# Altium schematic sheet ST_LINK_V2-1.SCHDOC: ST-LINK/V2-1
size A4; DocumentNumber: MB1263; Revision: C-04; SheetNumber: 10; SheetTotal: 11; Project: STM32MP157-EVAL
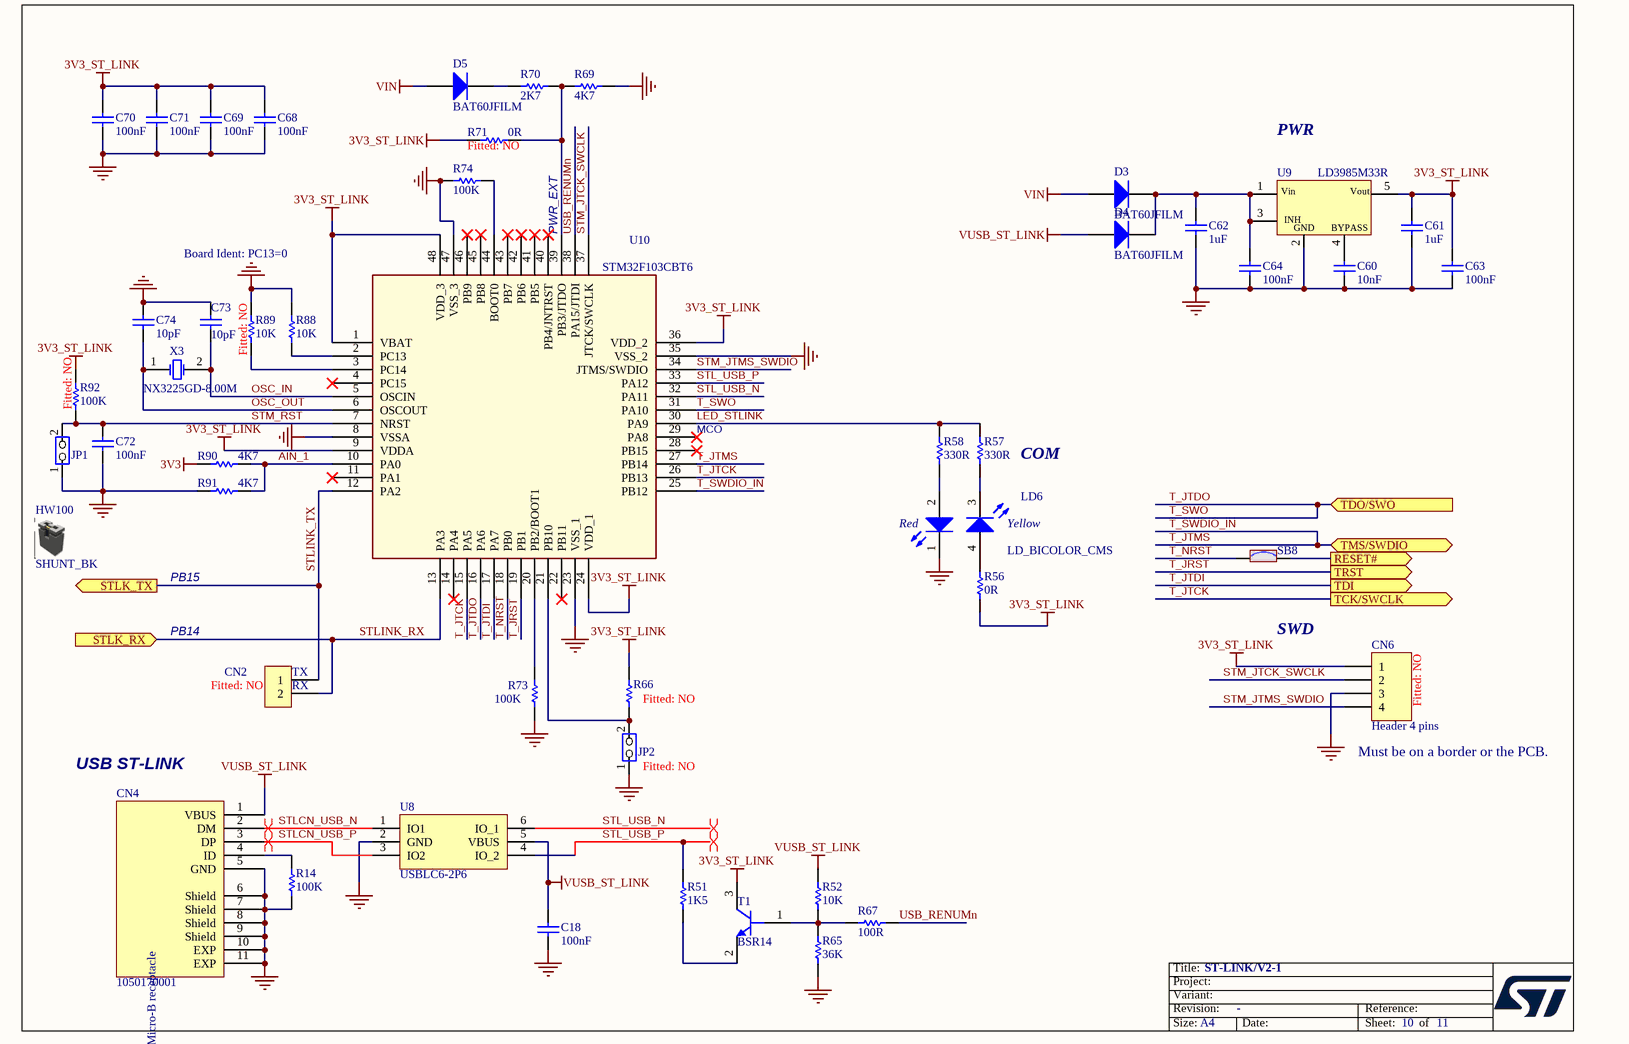
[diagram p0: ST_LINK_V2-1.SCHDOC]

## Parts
C18  100nF  [C0402]
C60  10nF  [C0603]
C61  1uF  [C0603]
C62  1uF  [C0603]
C63  100nF  [C0402]
C64  100nF  [C0402]
C68  100nF  [C0402]
C69  100nF  [C0402]
C70  100nF  [C0402]
C71  100nF  [C0402]
C72  100nF  [C0402]
C73  10pF  [C0402]
C74  10pF  [C0402]
CN2  Fitted: NO  [CON_SAMTEC_TSW-102-07-G-S]  (hidden comment: header 2 pins 2.54mm)
CN4  1050170001  [CON_USBMICROB_MOLEX_105017-0001_H2P90]
CN6  Header 4 pins  Fitted: NO  [CON_SAMTEC_TSW-104-07-G-S]
D3  BAT60JFILM  [DIO_SOD323]
D4  BAT60JFILM  [DIO_SOD323]
D5  BAT60JFILM  [DIO_SOD323]
HW100  SHUNT_BK  (mechanical)
JP1  Jumper_2.54mm  [CON_SAMTEC_TSW-102-07-G-S]  (value not drawn)
JP2  Fitted: NO  [CON_SAMTEC_TSW-102-07-G-S]  (hidden comment: Jumper_2.54mm)
LD6  LD_BICOLOR_CMS  [LED_BI-GR_HSMF-A201-A00J1]
R14  100K  [R0402]
R51  1K5  [R0402]
R52  10K  [R0402]
R56  0R  [R0402]
R57  330R  [R0402]
R58  330R  [R0402]
R65  36K  [R0402]
R66  Fitted: NO  [R0402]  (hidden comment: 1K)
R67  100R  [R0402]
R69  4K7  [R0402]
R70  2K7  [R0402]
R71  0R  Fitted: NO  [R0402]
R73  100K  [R0402]
R74  100K  [R0402]
R88  10K  [R0402]
R89  10K  Fitted: NO  [R0402]
R90  4K7  [R0402]
R91  4K7  [R0402]
R92  100K  Fitted: NO  [R0402]
SB8  SB_ON  [SOLDER-BRIDGE_R0603-0R]  (value not drawn)
T1  BSR14  [NPN_SOT23]
U8  USBLC6-2P6  [ESD_SOT666]
U9  LD3985M33R  [REG_SOT23-5L]
U10  STM32F103CBT6  [ICC_LQFP48_7X7_P050]
X3  NX3225GD-8.00M  [CRY_NX3225GD_2P]

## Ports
RESET# (out), STLK_RX (in), STLK_TX (out), TCK/SWCLK (out), TDI (out), TDO/SWO (in), TMS/SWDIO (bidir), TRST (out)

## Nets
3V3: R90.1
3V3_ST_LINK: C61.1 C63.2 C68.2 C69.2 C70.2 C71.2 CN6.1 R56.1 R66.1 R71.1 R92.2 T1.3(C) U9.5(Vout) U10.1(VBAT) U10.9(VDDA) U10.24(VDD_1) U10.36(VDD_2) U10.48(VDD_3)
GND: C18.1 C60.1 C61.2 C62.2 C63.1 C64.1 C68.1 C69.1 C70.1 C71.1 C72.2 C73.2 C74.2 CN4.5(GND) CN4.6(Shield) CN4.7(Shield) CN4.8(Shield) CN4.9(Shield) CN4.10(EXP) CN4.11(EXP) CN6.3 JP1.1(COMMON) JP2.1(COMMON) LD6.1(RED_cathode) R14.1 R65.2 R69.2 R73.1 R74.2 R88.2 R89.2 R91.1 U8.2(GND) U9.2(GND) U10.8(VSSA) U10.23(VSS_1) U10.35(VSS_2) U10.47(VSS_3)
VIN: D3.1(A) D5.1(A)
VUSB_ST_LINK: C18.2 CN4.1(VBUS) D4.1(A) R52.2 U8.5(VBUS)
AIN_1: R90.2 R91.2 U10.10(PA0)
LED_STLINK: R57.2 R58.2 U10.30(PA9)
OSC_IN: C73.1 U10.5(OSCIN) X3.2(OSC2)
OSC_OUT: C74.1 U10.6(OSCOUT) X3.1(OSC1)
RESET#: SB8.2 ; port RESET#
STL_USB_N: U8.6(IO_1) U10.32(PA11)
STL_USB_P: R51.1 U8.4(IO_2) U10.33(PA12)
STLCN_USB_N: CN4.2(DM) U8.1(IO1)
STLCN_USB_P: CN4.3(DP) U8.3(IO2)
STLINK_RX: CN2.2 U10.13(PA3) ; port STLK_RX
STLINK_TX: CN2.1 U10.12(PA2) ; port STLK_TX
STM_JTCK_SWCLK: CN6.2 U10.37(JTCK/SWCLK)
STM_JTMS_SWDIO: CN6.4 U10.34(JTMS/SWDIO)
STM_RST: C72.1 JP1.2(NO) R92.1 U10.7(NRST)
T_JRST: U10.19(PB1) ; port TRST
T_JTCK: U10.15(PA5) U10.26(PB13) ; port TCK/SWCLK
T_JTDI: U10.17(PA7) ; port TDI
T_JTDO: U10.16(PA6) U10.31(PA10) ; port TDO/SWO  [also labelled T_SWO]
T_JTMS: U10.25(PB12) U10.27(PB14) ; port TMS/SWDIO  [also labelled T_SWDIO_IN]
T_NRST: SB8.1 U10.18(PB0)
USB_RENUMn: R67.2 U10.38(PA15/JTDI)
NetC60_2: C60.2 U9.4(BYPASS)
NetC62_1: C62.1 C64.2 D3.2(K) D4.2(K) U9.1(Vin) U9.3(CE)
NetCN4_4: CN4.4(ID) R14.2
NetD5_2: D5.2(K) R70.1
NetJP2_2: JP2.2(NO) R66.2 U10.21(PB10)
NetLD6_2: LD6.2(Red_anode) R58.1
NetLD6_3: LD6.3(YellowGreen_cathode) R57.1
NetLD6_4: LD6.4(YellowGreen_anode) R56.2
NetR51_2: R51.2 T1.2(E)
NetR52_1: R52.1 R65.1 R67.1 T1.1(B)
NetR69_1: R69.1 R70.2 R71.2 U10.39(PB3/JTDO)
NetR73_2: R73.2 U10.20(PB2/BOOT1)
NetR74_1: R74.1 U10.44(BOOT0)
NetR88_1: R88.1 U10.2(PC13)
NetR89_1: R89.1 U10.3(PC14)

Not connected (* = marked no-connect by the designer): U10 4(PC15)* 11(PA1)* 14(PA4)* 22(PB11)* 28(PB15)* 29(PA8)* 40(PB4/JNTRST)* 41(PB5)* 42(PB6)* 43(PB7)* 45(PB8)* 46(PB9)*

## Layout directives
differential pair: (no net found under the mark), STL_USB_N, STL_USB_P

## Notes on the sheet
- PWR
- (near U10) PWR_EXT
- Board Ident: PC13=0
- (near U10) MCO
- (near R57) COM
- PB15
- PB14
- SWD
- (near CN2) TX
- (near CN2) RX
- USB ST-LINK
- (near CN6) Must be on a border or the PCB.

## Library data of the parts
C18 C63 C64 C68-C72 = Cap_100nF_X7R_10%_0402: Capacitor,100nF,16V,X7R,10%,0402,YAGEO; Manuf_Part_1: CC0402KRX7R7BB104; Fitted: YES; Ordered_By: Subcon
C60 = Cap_10nF_X7R_10%_0603: Capacitor,10nF,50V,X7R,10%,0603,YAGEO; Manuf_Part_1: CC0603KRX7R9BB103; Fitted: YES; Ordered_By: Subcon
C61 C62 = Cap_1uF_X5R_10%_0603: Capacitor,1uF,16V,X5R,10%,0603,YAGEO; Manuf_Part_1: CC0603KRX5R7BB105; Fitted: YES; Ordered_By: Subcon
C73 C74 = Cap_10pF_NPO_5%_0402: Capacitor,10pF,50V,NPO,5%,0402,YAGEO; Order_Code: CC0402JRNPO9BN100; Fitted: YES; Ordered_By: subcon
CN2 = Header 2 pins: Manuf_1: SAMTEC; Manuf_Part_2: 4711955140470; Manuf_2: KONTEC; Manuf_Part_1: TSW-102-07-x-S; Order_Code: 423-2841; Ordered_By: Subcon
CN4 = 1050170001: USB-MICRO-B, 1050170001, SMT, MOLEX; Fitted: YES; Ordered_By: Subcon
CN6 = Header 4: Header, 4-Pin; Manuf_1: Samtec; Manuf_Part_1: TSW-104-07-x-S; Ordered_By: Subcon
D3-D5 = BAT60JFILM: Manuf_1: STM; Ordered_By: Subcon; ECCN_US/EU: EAR99/NEC; Ref St: 9151097; Fitted: YES
HW100 = Shunt 2.54mm: SHUNT 2.54mm BLACK; Manuf_1: SAMTEC; Manuf_Part_1: SNT-100-BK-G; Fitted: YES; Ordered_By: Subcon
JP1 = TSW-102-07-x-S: Connector jumper 1 position; Manuf_1: SAMTEC; Manuf_Part_2: 4711955140470; Manuf_2: KONTEC; Order_Code: 423-2841; Fitted: YES; Ordered_By: Subcon
JP2 = TSW-102-07-x-S: Connector jumper 1 position; Manuf_1: SAMTEC; Manuf_Part_2: 4711955140470; Manuf_2: KONTEC; Order_Code: 423-2841; Ordered_By: Subcon
LD6 = LD_BICOLOR_CMS: Bicolor Led; Manuf_Part_1: HSMF-A201-A00J1; Manuf_1: Avago Technologies; Manuf_2: everluck; Manuf_Part_2: LE-RGW35280; Ordered_By: Subcon; ECCN_US/EU: EAR99/NEC; Fitted: YES
R14 R73 R74 = Res_100K_1%_0402: Resistor,100K,0402,1%,YAGEO; Manuf_Part_2: RT0402FRE07100KL; Manuf_Part_1: RC0402FR-07100KL; Fitted: YES; Ordered_By: Subcon
R51 = Res_1K5_1%_0402: Resistor,1K5,0402,1%,YAGEO; Manuf_Part_1: RC0402FR-071K5L; Fitted: YES; Ordered_By: Subcon
R52 R88 = Res_10K_1%_0402: Resistor,10K,0402,1%,YAGEO; Manuf_Part_1: RC0402FR-0710KL; Order_Code: 9239359RL; Fitted: YES; Ordered_By: Subcon
R56 = Res_0_5%_0402: Resistor,0R,0402,5%,YAGEO; Manuf_Part_1: RC0402JR-070RL; Order_Code: 2363467; Fitted: YES; Ordered_By: Subcon
R57 R58 = Res_330_1%_0402: Resistor,330R,0402,1%,YAGEO; Manuf_Part_1: RC0402FR-07330RL; Fitted: YES; Ordered_By: Subcon
R65 = Res_36K_1%_0402: Resistor,36K,0402,1%,YAGEO; Manuf_Part_1: RC0402FR-0736KL; Fitted: YES; Ordered_By: Subcon
R66 = Res_1K_1%_0402: Resistor,1K,0402,1%,YAGEO; Manuf_Part_1: RC0402FR-071KL; Ordered_By: Subcon
R67 = Res_100_1%_0402: Resistor,100R,0402,1%,YAGEO; Manuf_Part_1: RC0402FR-07100RL; Order_Code: 9239111; Fitted: YES; Ordered_By: Subcon
R69 R90 R91 = Res_4K7_1%_0402: Resistor,4K7,0402,1%,YAGEO; Manuf_Part_2: RT0402FRE074K7L; Manuf_Part_1: RC0402FR-074K7L; Fitted: YES; Ordered_By: Subcon
R70 = Res_2K7_1%_0402: Resistor,2K7,0402,1%,YAGEO; Manuf_Part_1: RC0402FR-072K7L; Fitted: YES; Ordered_By: Subcon
R71 = Res_0_5%_0402: Resistor,0R,0402,5%,YAGEO; Manuf_Part_1: RC0402JR-070RL; Order_Code: 2363467; Ordered_By: Subcon
R89 = Res_10K_1%_0402: Resistor,10K,0402,1%,YAGEO; Manuf_Part_1: RC0402FR-0710KL; Order_Code: 9239359RL; Ordered_By: Subcon
R92 = Res_100K_1%_0402: Resistor,100K,0402,1%,YAGEO; Manuf_Part_2: RT0402FRE07100KL; Manuf_Part_1: RC0402FR-07100KL; Ordered_By: Subcon
SB8 = SB_ON: Solder Bridge ON; Fitted: YES; Ordered_by: Subcon
T1 = 9013-SOT23_1: NPN Bipolar Transistor; Manuf_1: NXP; Order_Code: 1081310; ECCN_US/EU: EAR99/NEC; Fitted: YES; Ordered_By: Subcon
U8 = USBLC6-2P6: USB ESD protection; Manuf_1: STM; Ordered_By: Subcon; ECCN_US/EU: EAR99/NEC; Fitted: YES
U9 = LD3985M33R: Ultra low drop-low noise BiCMOS voltage, regulators low ESR capacitors compatible; Manuf_1: STM; Ordered_By: Subcon; Ref St: 9176161; ECCN_US/EU: EAR99/NEC; Fitted: YES
U10 = STM32F103CBT6: Medium-density performance line ARM-based 32-bit MCU with 128KB Flash; Manuf_1: STM; Ordered_By: Subcon; ECCN_US/EU: 3A991A2/NEC; Fitted: YES
X3 = XTAL_8M_NX3225GD: Crystal 8Mhz, 8pF, -+50PPM, SMD; Manuf_1: NDK; Order_Code: NX3225GD 8MHz EXS00A-CG04874; ECCN_US/EU: EAR99/NEC; NDK Ref: X3127326; Ref St: 9157029; Ordered_By: Subcon; Fitted: YES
